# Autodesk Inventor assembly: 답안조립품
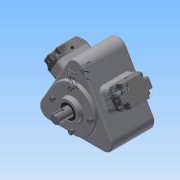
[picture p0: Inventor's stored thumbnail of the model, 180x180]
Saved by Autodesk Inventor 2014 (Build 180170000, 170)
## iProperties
Created: 2015-06
Part Number: 답안조립품
Document SubType Name: Assembly
Designer: Administrator
Mass: 5318.58 g
Surface Area: 2414.93 cm^2
Volume: 1564.62 cm^3
Density: 3.39928 g/cm^3
Author: Administrator
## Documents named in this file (20)
- C:\Users\Administrator\Desktop\350605V1044\답안조립품.iam
- C:\Users\Administrator\Desktop\350605V1044\본체.ipt
- C:\Users\Administrator\Desktop\350605V1044\앞커버.ipt
- C:\Users\Administrator\Desktop\350605V1044\오일실.ipt
- 오일실.ipt
- C:\Users\Administrator\Desktop\350605V1044\베어링 NA 4904.ipt
- 베어링 NA 4904.ipt
- C:\Users\Administrator\Desktop\350605V1044\편심축.ipt
- C:\Users\Administrator\Desktop\350605V1044\슬라이드.ipt
- C:\Users\Administrator\Desktop\350605V1044\부시.ipt
- C:\Users\Administrator\Desktop\350605V1044\헤더커버.ipt
- 헤더커버.ipt
- C:\Users\Administrator\Desktop\350605V1044\M4x0.5x16.ipt
- M4x0.5x16.ipt
- C:\Users\Administrator\Desktop\350605V1044\M6x0.7x20.ipt
- M6x0.7x20.ipt
- C:\Users\Administrator\Desktop\350605V1044\8 스프링.ipt
- C:\Users\Administrator\Desktop\350605V1044\9 스프링.ipt
- C:\Users\Administrator\Desktop\350605V1044\10 스프링.ipt
- C:\Users\Administrator\Desktop\350605V1044\11 스프링.ipt
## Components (18 placed, 7 different names)
1. 헤더커버:1
2. 헤더커버:2
3. M4x0.5x16:1
4. M4x0.5x16:2
5. M4x0.5x16:3
6. M4x0.5x16:4
7. M4x0.5x16:5
8. M4x0.5x16:6
9. M4x0.5x16:7
10. M4x0.5x16:8
11. 8 스프링:1
12. 9 스프링:1
13. 10 스프링:1
14. 11 스프링:1
15. M6x0.7x20:1
16. M6x0.7x20:2
17. M6x0.7x20:3
18. M6x0.7x20:4
